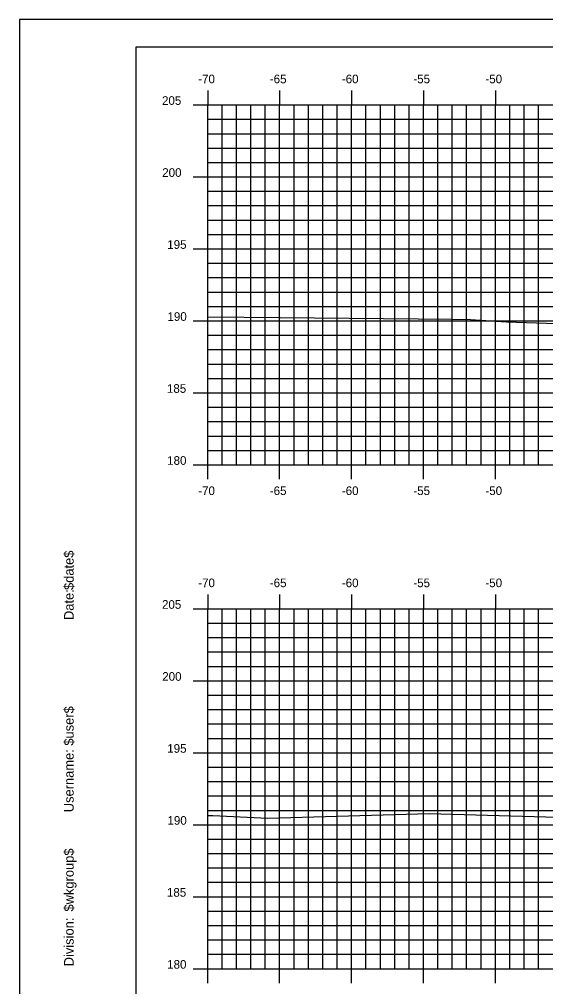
# Model space of a CAD drawing. Extents: x 1723764 to 1723936, y 458501 to 458611.
# Drawn here: x 1723764.4 to 1723801, y 458544 to 458611.2 of the extents above; entities that cross this region are included whole.
import ezdxf

# ---------------------------------------------------------------- set-up
doc = ezdxf.new("R2010")
doc.units = 0
for name, color, linetype in [('BORDER', 7, 'Continuous'), ('H_V ANNOTATION', 7, 'Continuous'), ('MAJOR', 7, 'Continuous'), ('MINOR', 7, 'Continuous'), ('PLOT BOUNDARY', 7, 'Continuous'), ('S_Roadway_Centerline', 7, 'Continuous')]:
    doc.layers.add(name, color=color, linetype=linetype)

msp = doc.modelspace()

# ---------------------------------------------------------------- linework, layer by layer
at = {"layer": 'BORDER'}
msp.add_lwpolyline([(1723772.542, 458504.254), (1723932.542, 458504.254), (1723932.542, 458609.254), (1723772.542, 458609.254)], close=True, dxfattribs=at)
at = {"layer": 'MAJOR'}
for p, q in [((1723777.542, 458606.256), (1723777.542, 458605.254)), ((1723782.542, 458606.256), (1723782.542, 458605.254)), ((1723787.542, 458606.256), (1723787.542, 458605.254)), ((1723792.542, 458606.256), (1723792.542, 458605.254)), ((1723797.542, 458606.256), (1723797.542, 458605.254)), ((1723776.54, 458605.254), (1723777.542, 458605.254)), ((1723777.542, 458605.254), (1723917.542, 458605.254)), ((1723777.542, 458580.254), (1723777.542, 458605.254)), ((1723777.542, 458580.254), (1723777.542, 458605.254)), ((1723777.542, 458605.254), (1723917.542, 458605.254)), ((1723782.542, 458580.254), (1723782.542, 458605.254)), ((1723787.542, 458580.254), (1723787.542, 458605.254)), ((1723792.542, 458580.254), (1723792.542, 458605.254)), ((1723797.542, 458580.254), (1723797.542, 458605.254)), ((1723776.54, 458600.254), (1723777.542, 458600.254)), ((1723777.542, 458600.254), (1723917.542, 458600.254)), ((1723776.54, 458595.254), (1723777.542, 458595.254)), ((1723777.542, 458595.254), (1723917.542, 458595.254)), ((1723776.54, 458590.254), (1723777.542, 458590.254)), ((1723777.542, 458590.254), (1723917.542, 458590.254)), ((1723776.54, 458585.254), (1723777.542, 458585.254)), ((1723777.542, 458585.254), (1723917.542, 458585.254)), ((1723776.54, 458580.254), (1723777.542, 458580.254)), ((1723777.542, 458580.254), (1723917.542, 458580.254)), ((1723777.542, 458580.254), (1723917.542, 458580.254)), ((1723777.542, 458579.252), (1723777.542, 458580.254)), ((1723782.542, 458579.252), (1723782.542, 458580.254)), ((1723787.542, 458579.252), (1723787.542, 458580.254)), ((1723792.542, 458579.252), (1723792.542, 458580.254)), ((1723797.542, 458579.252), (1723797.542, 458580.254)), ((1723777.542, 458571.256), (1723777.542, 458570.254)), ((1723782.542, 458571.256), (1723782.542, 458570.254)), ((1723787.542, 458571.256), (1723787.542, 458570.254)), ((1723792.542, 458571.256), (1723792.542, 458570.254)), ((1723797.542, 458571.256), (1723797.542, 458570.254)), ((1723776.54, 458570.254), (1723777.542, 458570.254)), ((1723777.542, 458570.254), (1723917.542, 458570.254)), ((1723777.542, 458545.254), (1723777.542, 458570.254)), ((1723777.542, 458545.254), (1723777.542, 458570.254)), ((1723777.542, 458570.254), (1723917.542, 458570.254)), ((1723782.542, 458545.254), (1723782.542, 458570.254)), ((1723787.542, 458545.254), (1723787.542, 458570.254)), ((1723792.542, 458545.254), (1723792.542, 458570.254)), ((1723797.542, 458545.254), (1723797.542, 458570.254)), ((1723776.54, 458565.254), (1723777.542, 458565.254)), ((1723777.542, 458565.254), (1723917.542, 458565.254)), ((1723776.54, 458560.254), (1723777.542, 458560.254)), ((1723777.542, 458560.254), (1723917.542, 458560.254)), ((1723776.54, 458555.254), (1723777.542, 458555.254)), ((1723777.542, 458555.254), (1723917.542, 458555.254)), ((1723776.54, 458550.254), (1723777.542, 458550.254)), ((1723777.542, 458550.254), (1723917.542, 458550.254)), ((1723776.54, 458545.254), (1723777.542, 458545.254)), ((1723777.542, 458545.254), (1723917.542, 458545.254)), ((1723777.542, 458545.254), (1723917.542, 458545.254)), ((1723777.542, 458544.252), (1723777.542, 458545.254)), ((1723782.542, 458544.252), (1723782.542, 458545.254)), ((1723787.542, 458544.252), (1723787.542, 458545.254)), ((1723792.542, 458544.252), (1723792.542, 458545.254)), ((1723797.542, 458544.252), (1723797.542, 458545.254))]:
    msp.add_line(p, q, dxfattribs=at)
at = {"layer": 'MINOR'}
for p, q in [((1723778.542, 458580.254), (1723778.542, 458605.254)), ((1723779.542, 458580.254), (1723779.542, 458605.254)), ((1723780.542, 458580.254), (1723780.542, 458605.254)), ((1723781.542, 458580.254), (1723781.542, 458605.254)), ((1723783.542, 458580.254), (1723783.542, 458605.254)), ((1723784.542, 458580.254), (1723784.542, 458605.254)), ((1723785.542, 458580.254), (1723785.542, 458605.254)), ((1723786.542, 458580.254), (1723786.542, 458605.254)), ((1723788.542, 458580.254), (1723788.542, 458605.254)), ((1723789.542, 458580.254), (1723789.542, 458605.254)), ((1723790.542, 458580.254), (1723790.542, 458605.254)), ((1723791.542, 458580.254), (1723791.542, 458605.254)), ((1723793.542, 458580.254), (1723793.542, 458605.254)), ((1723794.542, 458580.254), (1723794.542, 458605.254)), ((1723795.542, 458580.254), (1723795.542, 458605.254)), ((1723796.542, 458580.254), (1723796.542, 458605.254)), ((1723798.542, 458580.254), (1723798.542, 458605.254)), ((1723799.542, 458580.254), (1723799.542, 458605.254)), ((1723800.542, 458580.254), (1723800.542, 458605.254)), ((1723777.542, 458604.254), (1723917.542, 458604.254)), ((1723777.542, 458604.254), (1723778.544, 458604.254)), ((1723777.542, 458603.254), (1723917.542, 458603.254)), ((1723777.542, 458603.254), (1723778.544, 458603.254)), ((1723777.542, 458602.254), (1723917.542, 458602.254)), ((1723777.542, 458602.254), (1723778.544, 458602.254)), ((1723777.542, 458601.254), (1723917.542, 458601.254)), ((1723777.542, 458601.254), (1723778.544, 458601.254)), ((1723777.542, 458599.254), (1723917.542, 458599.254)), ((1723777.542, 458599.254), (1723778.544, 458599.254)), ((1723777.542, 458598.254), (1723917.542, 458598.254)), ((1723777.542, 458598.254), (1723778.544, 458598.254)), ((1723777.542, 458597.254), (1723917.542, 458597.254)), ((1723777.542, 458597.254), (1723778.544, 458597.254)), ((1723777.542, 458596.254), (1723917.542, 458596.254)), ((1723777.542, 458596.254), (1723778.544, 458596.254)), ((1723777.542, 458594.254), (1723917.542, 458594.254)), ((1723777.542, 458594.254), (1723778.544, 458594.254)), ((1723777.542, 458593.254), (1723917.542, 458593.254)), ((1723777.542, 458593.254), (1723778.544, 458593.254)), ((1723777.542, 458592.254), (1723917.542, 458592.254)), ((1723777.542, 458592.254), (1723778.544, 458592.254)), ((1723777.542, 458591.254), (1723917.542, 458591.254)), ((1723777.542, 458591.254), (1723778.544, 458591.254)), ((1723777.542, 458589.254), (1723917.542, 458589.254)), ((1723777.542, 458589.254), (1723778.544, 458589.254)), ((1723777.542, 458588.254), (1723917.542, 458588.254)), ((1723777.542, 458588.254), (1723778.544, 458588.254)), ((1723777.542, 458587.254), (1723917.542, 458587.254)), ((1723777.542, 458587.254), (1723778.544, 458587.254)), ((1723777.542, 458586.254), (1723917.542, 458586.254)), ((1723777.542, 458586.254), (1723778.544, 458586.254)), ((1723777.542, 458584.254), (1723917.542, 458584.254)), ((1723777.542, 458584.254), (1723778.544, 458584.254)), ((1723777.542, 458583.254), (1723917.542, 458583.254)), ((1723777.542, 458583.254), (1723778.544, 458583.254)), ((1723777.542, 458582.254), (1723917.542, 458582.254)), ((1723777.542, 458582.254), (1723778.544, 458582.254)), ((1723777.542, 458581.254), (1723917.542, 458581.254)), ((1723777.542, 458581.254), (1723778.544, 458581.254)), ((1723778.542, 458545.254), (1723778.542, 458570.254)), ((1723779.542, 458545.254), (1723779.542, 458570.254)), ((1723780.542, 458545.254), (1723780.542, 458570.254)), ((1723781.542, 458545.254), (1723781.542, 458570.254)), ((1723783.542, 458545.254), (1723783.542, 458570.254)), ((1723784.542, 458545.254), (1723784.542, 458570.254)), ((1723785.542, 458545.254), (1723785.542, 458570.254)), ((1723786.542, 458545.254), (1723786.542, 458570.254)), ((1723788.542, 458545.254), (1723788.542, 458570.254)), ((1723789.542, 458545.254), (1723789.542, 458570.254)), ((1723790.542, 458545.254), (1723790.542, 458570.254)), ((1723791.542, 458545.254), (1723791.542, 458570.254)), ((1723793.542, 458545.254), (1723793.542, 458570.254)), ((1723794.542, 458545.254), (1723794.542, 458570.254)), ((1723795.542, 458545.254), (1723795.542, 458570.254)), ((1723796.542, 458545.254), (1723796.542, 458570.254)), ((1723798.542, 458545.254), (1723798.542, 458570.254)), ((1723799.542, 458545.254), (1723799.542, 458570.254)), ((1723800.542, 458545.254), (1723800.542, 458570.254)), ((1723777.542, 458569.254), (1723917.542, 458569.254)), ((1723777.542, 458569.254), (1723778.544, 458569.254)), ((1723777.542, 458568.254), (1723917.542, 458568.254)), ((1723777.542, 458568.254), (1723778.544, 458568.254)), ((1723777.542, 458567.254), (1723917.542, 458567.254)), ((1723777.542, 458567.254), (1723778.544, 458567.254)), ((1723777.542, 458566.254), (1723917.542, 458566.254)), ((1723777.542, 458566.254), (1723778.544, 458566.254)), ((1723777.542, 458564.254), (1723917.542, 458564.254)), ((1723777.542, 458564.254), (1723778.544, 458564.254)), ((1723777.542, 458563.254), (1723917.542, 458563.254)), ((1723777.542, 458563.254), (1723778.544, 458563.254)), ((1723777.542, 458562.254), (1723917.542, 458562.254)), ((1723777.542, 458562.254), (1723778.544, 458562.254)), ((1723777.542, 458561.254), (1723917.542, 458561.254)), ((1723777.542, 458561.254), (1723778.544, 458561.254)), ((1723777.542, 458559.254), (1723917.542, 458559.254)), ((1723777.542, 458559.254), (1723778.544, 458559.254)), ((1723777.542, 458558.254), (1723917.542, 458558.254)), ((1723777.542, 458558.254), (1723778.544, 458558.254)), ((1723777.542, 458557.254), (1723917.542, 458557.254)), ((1723777.542, 458557.254), (1723778.544, 458557.254)), ((1723777.542, 458556.254), (1723917.542, 458556.254)), ((1723777.542, 458556.254), (1723778.544, 458556.254)), ((1723777.542, 458554.254), (1723917.542, 458554.254)), ((1723777.542, 458554.254), (1723778.544, 458554.254)), ((1723777.542, 458553.254), (1723917.542, 458553.254)), ((1723777.542, 458553.254), (1723778.544, 458553.254)), ((1723777.542, 458552.254), (1723917.542, 458552.254)), ((1723777.542, 458552.254), (1723778.544, 458552.254)), ((1723777.542, 458551.254), (1723917.542, 458551.254)), ((1723777.542, 458551.254), (1723778.544, 458551.254)), ((1723777.542, 458549.254), (1723917.542, 458549.254)), ((1723777.542, 458549.254), (1723778.544, 458549.254)), ((1723777.542, 458548.254), (1723917.542, 458548.254)), ((1723777.542, 458548.254), (1723778.544, 458548.254)), ((1723777.542, 458547.254), (1723917.542, 458547.254)), ((1723777.542, 458547.254), (1723778.544, 458547.254)), ((1723777.542, 458546.254), (1723917.542, 458546.254)), ((1723777.542, 458546.254), (1723778.544, 458546.254))]:
    msp.add_line(p, q, dxfattribs=at)
at = {"layer": 'PLOT BOUNDARY'}
msp.add_lwpolyline([(1723764.449, 458501.195), (1723934.449, 458501.195), (1723934.449, 458611.195), (1723764.449, 458611.195)], close=True, dxfattribs=at)
at = {"layer": 'S_Roadway_Centerline'}
for points in [[(1723777.542, 458590.535), (1723782.572, 458590.478), (1723794.565, 458590.362), (1723795.815, 458590.342), (1723798.304, 458590.194), (1723814.321, 458589.653), (1723828.082, 458589.474), (1723834.118, 458589.453), (1723843.37, 458589.361), (1723853.307, 458588.898), (1723862.561, 458588.74), (1723874.103, 458588.626), (1723880.292, 458588.403), (1723889.466, 458587.592), (1723891.167, 458587.447), (1723892.536, 458587.426), (1723903.57, 458587.401), (1723913.068, 458587.172), (1723915.267, 458587.202), (1723917.542, 458586.995)], [(1723777.542, 458555.901), (1723777.899, 458555.886), (1723781.729, 458555.712), (1723784.914, 458555.809), (1723792.946, 458556.04), (1723804.299, 458555.71), (1723805.143, 458555.656), (1723805.732, 458555.623), (1723817.844, 458555.138), (1723827.379, 458554.731), (1723828.288, 458554.733), (1723838.5, 458554.836), (1723849.73, 458554.584), (1723856.129, 458554.317), (1723863.147, 458553.81), (1723870.978, 458553.613), (1723876.204, 458553.497), (1723881.901, 458553.314), (1723891.771, 458553.149), (1723909.916, 458552.356), (1723912.425, 458552.215), (1723917.542, 458552.075)]]:
    msp.add_lwpolyline(points, dxfattribs=at)

# ---------------------------------------------------------------- texts
at = {"layer": 'BORDER'}
for s, p in [('$date$', (1723768.227, 458571.559)), ('Date:', (1723768.227, 458569.471)), ('$user$', (1723768.227, 458560.746)), ('Username:', (1723768.227, 458556.122)), ('$wkgroup$', (1723768.227, 458549.224)), ('Division:', (1723768.227, 458545.42))]:
    msp.add_text(s, height=0.6696, rotation=90, dxfattribs=at).set_placement(p)
at = {"layer": 'H_V ANNOTATION'}
for s, p in [('-70', (1723776.884, 458606.754)), ('-65', (1723781.86, 458606.754)), ('-60', (1723786.868, 458606.754)), ('-55', (1723791.838, 458606.754)), ('-50', (1723796.846, 458606.754)), ('205', (1723774.367, 458605.254)), ('200', (1723774.383, 458600.254)), ('195', (1723774.731, 458595.254)), ('190', (1723774.747, 458590.254)), ('185', (1723774.709, 458585.254)), ('180', (1723774.725, 458580.254)), ('-70', (1723776.884, 458578.154)), ('-65', (1723781.86, 458578.154)), ('-60', (1723786.868, 458578.154)), ('-55', (1723791.838, 458578.154)), ('-50', (1723796.846, 458578.154)), ('-70', (1723776.884, 458571.754)), ('-65', (1723781.86, 458571.754)), ('-60', (1723786.868, 458571.754)), ('-55', (1723791.838, 458571.754)), ('-50', (1723796.846, 458571.754)), ('205', (1723774.367, 458570.254)), ('200', (1723774.383, 458565.254)), ('195', (1723774.731, 458560.254)), ('190', (1723774.747, 458555.254)), ('185', (1723774.709, 458550.254)), ('180', (1723774.725, 458545.254))]:
    msp.add_text(s, height=0.6, dxfattribs=at).set_placement(p)
at = {"layer": 'MAJOR'}
for p in [(1723777.537, 458580.254), (1723777.537, 458545.254)]:
    msp.add_text('-', height=0.006, dxfattribs=at).set_placement(p)

doc.saveas('drawing.dxf')
